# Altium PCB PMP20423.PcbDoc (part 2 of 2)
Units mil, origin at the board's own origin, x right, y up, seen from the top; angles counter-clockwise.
Board outline 2175 x 2115 mil, 4 copper layers (Top Layer, Signal Layer 1, Signal Layer 2, Bottom Layer), stack 82.634 mil thick; 73 components, 45 nets, 246 pads, 105 vias.
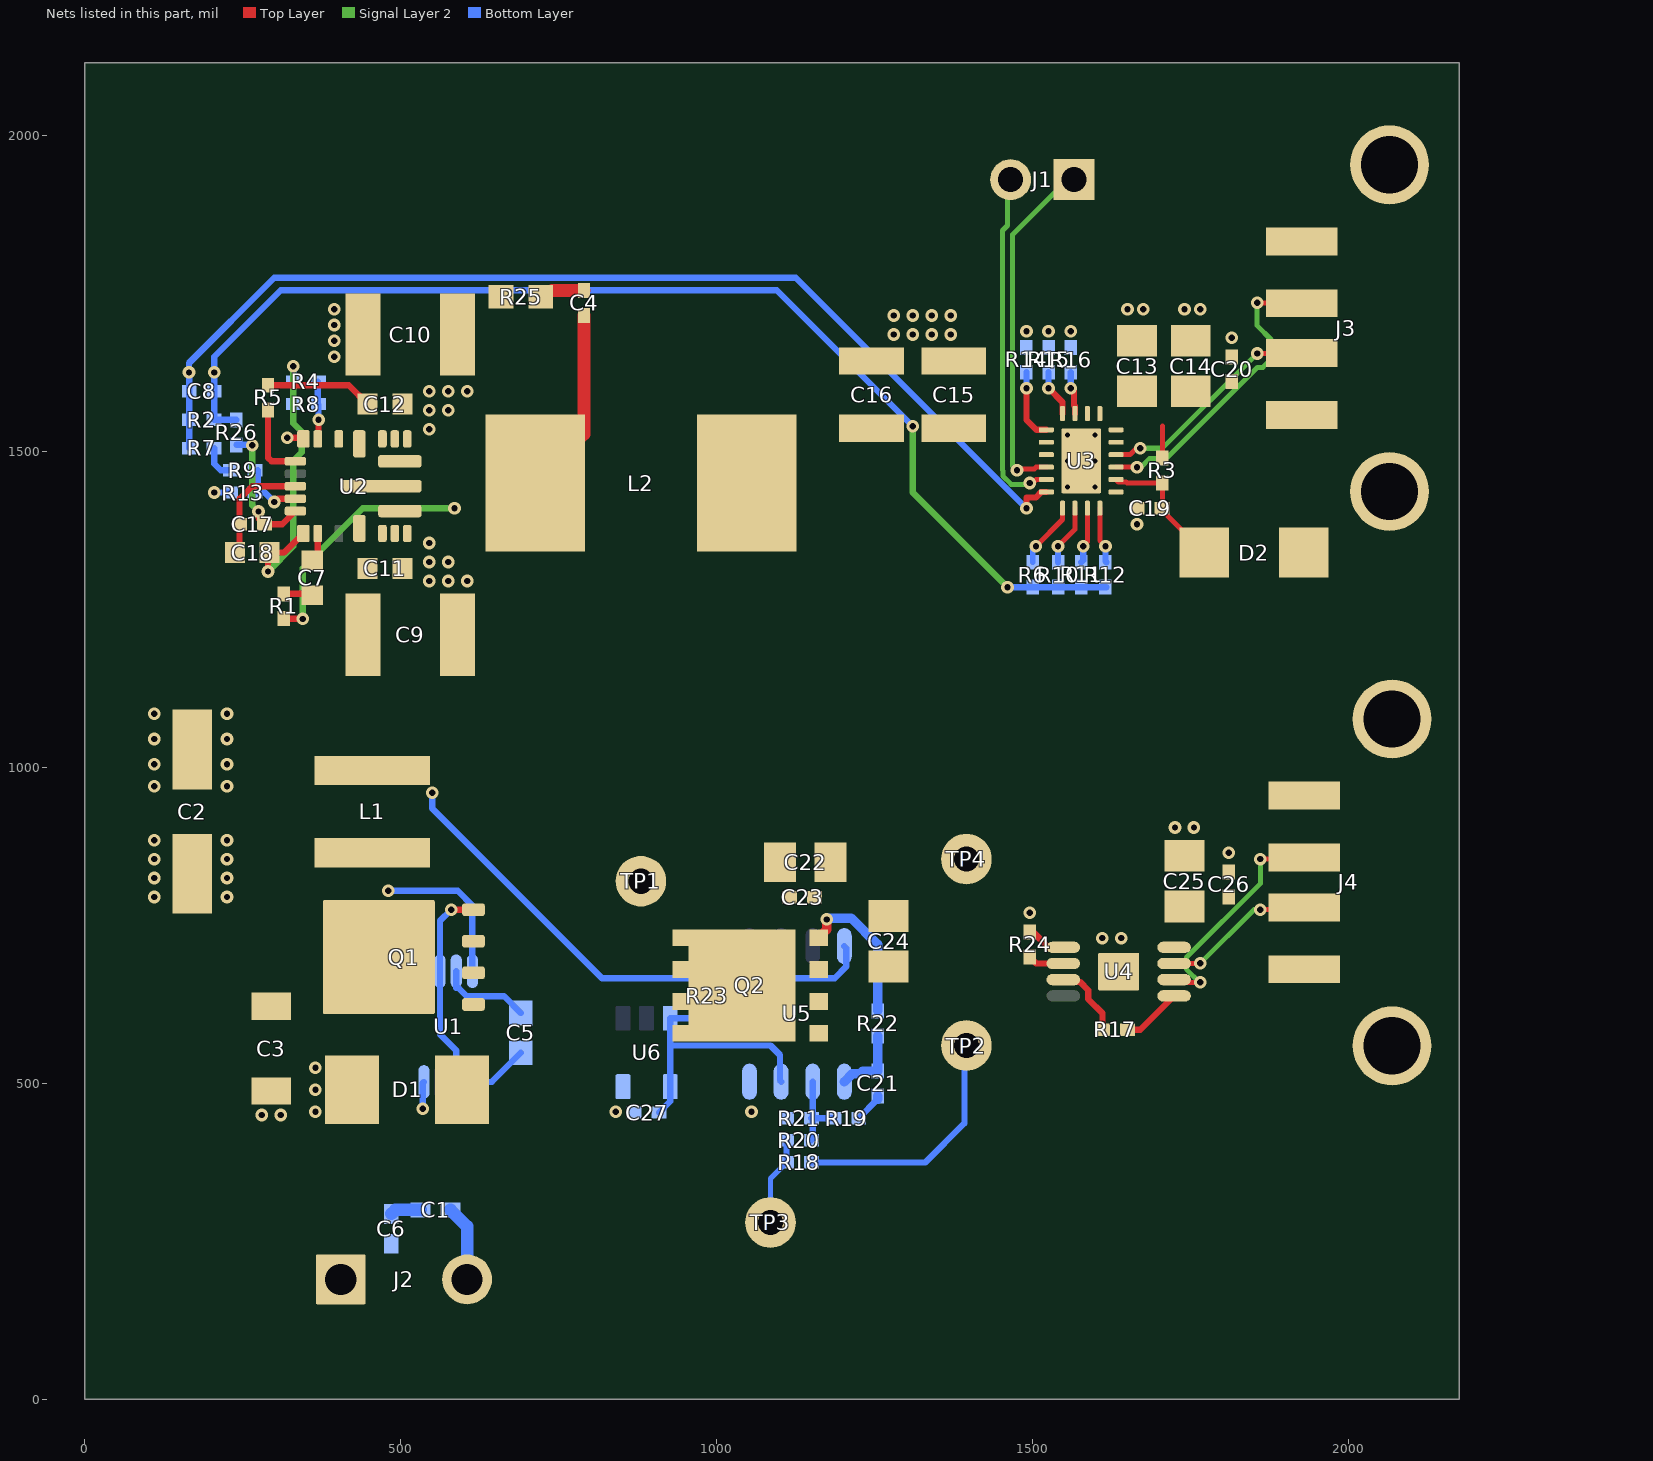
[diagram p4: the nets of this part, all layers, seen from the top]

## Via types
v1: diameter 20, hole 10, Top Layer to Bottom Layer, tented both sides, 99 vias
v2: diameter 19.68, hole 7.87, Top Layer to Bottom Layer, 6 vias

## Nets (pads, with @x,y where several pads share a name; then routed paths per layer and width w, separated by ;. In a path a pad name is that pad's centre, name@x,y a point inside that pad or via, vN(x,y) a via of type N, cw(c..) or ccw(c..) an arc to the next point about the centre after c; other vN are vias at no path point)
5VX: C8.1 C15.1 C16.1 C22.1 C23.1 L2.2 Q2.5 Q2.6 Q2.7 Q2.8 Q2.10 R2.2 R6.2 R10.2 R11.2 R12.2 R26.1 TP1.1 U3.2 U3.3 | length 1846.6
  Signal Layer 2 w10: v1(1310,1540) 1310,1435 v1(1460,1285)
  Bottom Layer w10: R26.1@240,1549.68 239.68,1550 R2.2@204.69,1550 205,1550.31 v1(205,1625) 205,1650 310,1755 1095,1755 v1(1310,1540) ; v1@1460.31,1285.31 1486.65,1285.31 1531.65,1285.31 R11.2@1576.65,1285.31 R12.2@1616.65,1285.31
CS: C8.2 R2.1 R7.2 U3.6 | length 1719
  Top Layer w10: v1(1490,1410) 1490,1427 1504.53,1427 1513.31,1435.79 U3.6@1521.54,1435.79
  Bottom Layer w10: v1(165,1625) 165,1640 300,1775 1125,1775 v1(1490,1410) ; R7.2@165.31,1505 C8.2@165.31,1595 v1@165.31,1624.69
DM1: J3.2 U3.14 | length 354.1
  Top Layer w8: U3.14@1631.77,1494.84 1653.73,1494.84 v1@1663.89,1505 ; v1(1855,1655) 1924.78,1655 J3.2@1925.41,1655.63
  Signal Layer 2 w8: v1(1670,1505) 1705,1505 v1(1855,1655)
DM1_H: J1.1 U3.4 | length 557.6
  Top Layer w8: v1(1475,1470) 1477.47,1472.47 1502.47,1472.47 1505.16,1475.16 U3.4@1521.54,1475.16
  Signal Layer 2 w8: v1(1475,1470) 1468,1477 1468,1843 1555,1930 J1.1@1565,1930
DP1: J3.3 U3.13 | length 484.8
  Top Layer w8: U3.13@1631.77,1475.16 v1@1664.84,1475.16 ; v1(1855,1735) 1924.78,1735 J3.3@1925.41,1734.37
  Signal Layer 2 w8: v1(1665,1475) 1671.11,1475 1685.11,1489 1711.63,1489 1855.63,1633 1864.11,1633 1877,1645.89 1877,1677 1855,1699 v1(1855,1735)
DP1_H: J1.2 U3.5 | length 554
  Top Layer w8: v1(1495,1450) 1500,1450 1505.47,1455.47 U3.5@1521.54,1455.47
  Signal Layer 2 w8: J1.2@1470,1930 1460,1920 1460,1857.63 1452,1849.63 1452,1470.37 1453,1469.37 1453,1460.89 1465.89,1448 1493,1448 v1(1495,1450)
GND: C2.2 C3.2 C6.2 C9.2 C10.2 C11.2 C12.2 C13.2 C14.2 C15.2 C16.2 C17.1 C18.2 C19.2 C20.2 C22.2 C23.2 C24.2 C25.2 C26.2 C27.2 D1.1 D2.1 J2.1 J3.4 J3.5 J3.6 J4.4 J4.5 J4.6 R8.1 R13.1 R14.1 R15.1 R16.1 R21.1 R24.1 R25.1 TP4.1 U2.5 U2.6 U2.7 U2.8 U2.10 U2.11 U2.12 U2.13 U2.17 U2.20 U3.11 U3.17 U3.18 U3.21@1576.65,1485 U4.1 U4.9 U5.4 U6.5 | length 295.8
  Top Layer w10: C18.2@235,1345 245,1355 245,1425 265,1445 312.48,1445 U2.20@333.19,1445 ; v1(320.39,1521.77) 344.02,1521.77 U2.17@345.98,1519.8 ; R24.1@1495,739.68 1500.32,739.68 1524.61,715.39 U4.1@1548.4,715.39
  Bottom Layer w10: v1(205,1435) R13.1@230.32,1435
  other v1: 280,450 310,450 365,455 840,455 1055,455 365,490 365,525 1610,730 1640,730 1495,770 110,795 225,795 110,825 225,825 110,855 225,855 1810,865 110,885 225,885 1725,905 1755,905 545,1295 575,1295 605,1295 545,1325 575,1325 545,1355 1665,1385 545,1535 545,1565 575,1565 545,1595 575,1595 605,1595 1815,1680 1280,1685 1310,1685 1340,1685 1370,1685 1490,1690 1525,1690 1560,1690 1280,1715 1310,1715 1340,1715 1370,1715 1650,1725 1675,1725 1740,1725 1765,1725
  other v2: 1555,1443.66 1598.31,1443.66 1555,1485 1598.31,1485 1555,1526.34 1598.31,1526.34
NetC1_2: C1.2 C6.1 | length 49
  Bottom Layer w20: C6.1@485,293.62 491.38,300 C1.2@531.38,300
NetC3_1: C3.1 L1.1 Q1.5 Q1.6 Q1.7 Q1.8 Q1.9@465.43,700 U1.8 | length 247.1
  Bottom Layer w10: v1(480,805) 590,805 613.39,781.61 U1.8@613.39,677.6
NetC4_1: C4.1 L2.1 R1.1 U2.9 | length 686.4
  Top Layer w10: R1.1@315,1235.32 v1@344.68,1235.32
  Top Layer w20: L2.1@712.68,1450 790,1527.32 C4.1@790,1715.32
  Signal Layer 2 w10: v1(345,1235) 345,1315 390,1360 440,1410 v1(585,1410)
NetC4_2: C4.2 R25.2 | length 64
  Top Layer w10: R25.2@730,1745 R25.2@739.69,1754.69
  Top Layer w20: R25.2@739.69,1754.69 C4.2@790,1754.69
NetC5_1: C5.1 U1.7 | length 145.3
  Bottom Layer w10: U1.7@587.8,677.6 587.8,651.02 591.53,651.02 591.53,650.83 604.33,638.02 663.47,638.02 C5.1@690,611.5
NetC5_2: C5.2 U1.1 | length 95.7
  Bottom Layer w10: U1.1@613.39,502.4 643.9,502.4 C5.2@690,548.5
NetC7_1: C7.1 R1.2 | length 45.9
  Top Layer w10: R1.2@315,1274.69 357.76,1274.69 C7.1@360,1272.44
NetC7_2: C7.2 U2.2 | length 46.2
  Top Layer w10: C7.2@360,1327.56 368.62,1336.18 U2.2@368.62,1370.2
NetC17_2: C17.2 R26.2 U2.22 | length 211
  Top Layer w10: v1(275,1405) 275,1394.69 C17.2@284.69,1385 ; C17.2@288.62,1385 312.56,1385 U2.22@333.19,1405.63
  Signal Layer 2 w10: v1(265,1510) 265,1415 v1(275,1405)
  Bottom Layer w10: R26.2@240,1510.31 v1@264.69,1510.31
NetC19_1: C19.1 D2.2 R3.1 U3.12 | length 213.4
  Top Layer w8: U3.12@1631.77,1455.47 1635.52,1451.72 1647.4,1451.72 1648.81,1450.32 R3.1@1705,1450.32 1705,1410.32 C19.1@1704.68,1410 1704.68,1406.57 D2.2@1771.26,1340
NetC21_1: C21.1 R22.1 U5.1 | length 115.8
  Bottom Layer w15: U5.1@1201.86,502.72 1214.15,515 1226.45,515 1231.14,519.68 C21.1@1255,519.68 R22.1@1255,575.32
NetC21_2: C21.2 R19.2 | length 47.9
  Bottom Layer w10: R19.2@1224.69,445 C21.2@1255,475.31
  Bottom Layer w15: C21.2@1255,475.31 C21.2@1255,480.31
NetC24_1: C24.1 Q2.1 Q2.2 Q2.3 R17.2 R18.2 TP2.1 U4.3 | length 504.3
  Top Layer w10: U4.3@1548.4,664.2 1557.26,664.2 1560.99,660.47 1575.17,660.47 1587.98,647.67 1587.98,633.49 1610.31,611.15 R17.2@1610.31,585
  Bottom Layer w10: R18.2@1149.69,375 1330,375 1391.86,436.86 TP2.1@1391.86,555
NetC27_1: C27.1 R23.1 U5.3 U6.3 U6.4 | length 505.4
  Bottom Layer w10: C27.1@908.75,454 926.46,471.72 U6.4@926.46,494.87 ; R23.1@984.06,611.44 975.76,603.13 U6.3@926.46,603.13 U6.4@926.46,494.87 ; U5.3@1101.86,502.72 1100,504.58 1100,545 1085,560 926.46,560 U6.4@926.46,494.87
NetJ4_2: J4.2 U4.7 | length 242.3
  Top Layer w8: U4.7@1723.6,689.8 v1@1764.8,689.8 ; v1(1860,775) 1925.78,775 J4.2@1929.41,778.63
  Signal Layer 2 w8: v1(1765,690) 1850,775 v1(1860,775)
NetJ4_3: J4.3 U4.6 | length 365.7
  Top Layer w8: U4.6@1723.6,664.2 1727.8,660 v1(1765,660) ; v1(1860,855) 1927.04,855 J4.3@1929.41,857.37
  Signal Layer 2 w8: v1@1763.89,660 1743,680.89 1743,699.11 1860,816.11 v1(1860,855)
NetQ1_4: Q1.4 U1.2 U1.6 | length 325.6
  Top Layer w10: v1(580,775) Q1.4@615.04,775
  Bottom Layer w10: v1(580,775) 562.2,757.2 U1.6@562.2,677.6 562.2,577.8 587.8,552.2 U1.2@587.8,502.4
NetQ2_4: Q2.4 R22.2 | length 238.2
  Top Layer w15: Q2.4@1161.17,730.49 1174.11,743.43 v1(1174.11,759.53)
  Bottom Layer w15: v1(1174.11,759.53) 1175.91,761.33 1213.17,761.33 1254.5,720 1254.5,615.18 R22.2@1255,614.69
NetR4_1: R4.1 R8.2 U2.16 | length 91.3
  Top Layer w10: U2.16@368.83,1519.8 370,1520.98 v1(370,1550)
  Bottom Layer w10: R4.1@368.62,1610 368.62,1575 370,1573.62 v1(370,1550)
NetR5_2: R5.2 U2.18 | length 120.8
  Top Layer w10: R5.2@290,1565.31 290,1490 295.63,1484.37 U2.18@333.19,1484.37
NetR6_1: R6.1 U3.7 | length 98
  Top Layer w8: v1(1505,1350) 1547.13,1392.13 U3.7@1547.13,1410.2
  Bottom Layer w8: R6.1@1500,1324.68 v1@1500,1345
NetR7_1: R7.1 R9.2 | length 54.6
  Bottom Layer w10: R7.1@204.68,1505 204.68,1480.32 215,1470 R9.2@230.31,1470
NetR9_1: R9.1 R13.2 U2.21 | length 95.5
  Top Layer w10: v1@305.31,1425.31 U2.21@333.19,1425.31
  Bottom Layer w10: R9.1@273.62,1470 273.62,1435 285,1435 v1(300,1420)
NetR10_1: R10.1 U3.8 | length 96.6
  Top Layer w8: v1(1540,1350) 1566.81,1376.81 U3.8@1566.81,1410.2
  Bottom Layer w10: R10.1@1540,1324.68 v1(1540,1350)
NetR11_1: R11.1 U3.9 | length 80.4
  Top Layer w8: v1@1586.5,1356.5 U3.9@1586.5,1410.2
  Bottom Layer w10: R11.1@1576.65,1324.68 1580,1328.03 v1(1580,1350)
NetR12_1: R12.1 U3.10 | length 89.8
  Top Layer w8: U3.10@1606.18,1410.2 1606.18,1358.82 v1(1615,1350)
  Bottom Layer w10: v1(1615,1350) 1615,1326.34 R12.1@1616.65,1324.68
NetR14_2: R14.2 U3.1 | length 113.4
  Top Layer w10: v1(1490,1600) 1490,1550 1505.79,1534.21 U3.1@1521.54,1534.21
  Bottom Layer w10: v1(1490,1600) R14.2@1490,1625.31
NetR15_2: R15.2 U3.20 | length 74.7
  Top Layer w10: v1(1525,1600) 1547.13,1577.87 U3.20@1547.13,1559.8
  Bottom Layer w10: v1(1525,1600) R15.2@1525,1625.31
NetR16_2: R16.2 U3.19 | length 68.3
  Top Layer w10: v1(1560,1600) 1565.13,1594.87 1565.13,1573.3 1566.81,1571.61 U3.19@1566.81,1559.8
  Bottom Layer w10: v1(1560,1600) R16.2@1560,1625.31
NetR17_1: R17.1 U4.5 | length 96.1
  Top Layer w10: R17.1@1649.68,585 1669.98,585 U4.5@1723.6,638.61
NetR18_1: R18.1 R20.2 TP3.1 | length 140.5
  Bottom Layer w8: TP3.1@1085,280 1085,349.68 R18.1@1110.32,375
  Bottom Layer w10: R18.1@1110.32,375 R20.2@1110.31,410
NetR19_1: R19.1 R20.1 R21.2 U5.2 | length 129.2
  Bottom Layer w10: R20.1@1149.68,410 1151.86,412.18 R21.2@1151.86,445 ; R21.2@1149.69,445 R21.2@1151.86,445 ; U5.2@1151.86,502.72 R21.2@1151.86,445 ; R19.1@1185.32,445 R21.2@1151.86,445
NetR24_2: R24.2 U4.2 | length 57.8
  Top Layer w10: R24.2@1495,700.31 1505.52,689.8 U4.2@1548.4,689.8
VBATT: C1.1 D1.2 J2.2 Q1.1 Q1.2 Q1.3 U1.4 | length 139
  Bottom Layer w10: v1(535,460) 535,500.79 U1.4@536.61,502.4
  Bottom Layer w20: C1.1@578.62,300 605,273.62 J2.2@605,215
VBUS_LOCAL: C25.1 C26.1 J4.1 U4.8
VBUS_REMOTE: C13.1 C14.1 C20.1 J3.1 R3.2 U3.15 U3.16 | length 50.3
  Top Layer w8: R3.2@1705,1489.69 1705,1540
VCC: C18.1 R4.2 U2.1 | length 472.7
  Top Layer w10: v1(290,1310) 290,1333.5 296.5,1340 315.79,1340 U2.1@345.98,1370.2 U2.1@345.98,1369.49
  Signal Layer 2 w10: v1(290,1310) 330,1350 330,1485.46 343.39,1498.85 343.39,1531.3 330,1544.69 v1(330,1635)
  Bottom Layer w10: R4.2@330.31,1610 v1@330.31,1634.69
VIN: C2.1 C9.1 C10.1 C11.1 C12.1 L1.2 R5.1 R23.2 U2.4 U2.14 U2.15 U5.8 | length 1002.2
  Top Layer w10: R5.1@290,1604.68 417.76,1604.68 C12.1@447.44,1575
  Bottom Layer w10: v1(550,960) 550,935 818.44,666.56 R23.2@984.06,666.56 1186.56,666.56 1205,685 1205,714.15 U5.8@1201.86,717.28
  other v1: 110,970 225,970 110,1005 225,1005 110,1045 225,1045 110,1085 225,1085 395,1650 395,1675 395,1700 395,1725
pads on no net: Q1.9@449.88,642.91 Q1.9@449.88,700 Q1.9@449.88,757.09 Q1.9@483.35,700 Q1.9@519.96,642.91 Q1.9@519.96,700 Q1.9@519.96,757.09 U1.3 U1.5 U2.3 U2.4A U2.4B U2.8A U2.8B U2.9A U2.9B U2.9C U2.9D U2.10A U2.10B U2.14A U2.14B U2.19 U3.21@1576.65,1458.43 U3.21@1576.65,1511.57 U4.4 U5.5 U5.6 U5.7 U6.1 U6.2

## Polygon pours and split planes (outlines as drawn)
GND on Top Layer "GND_L01_P022" (solid, remove dead copper, pour order 22): 0,2115 0,0 2175,0 2175,2115
VBUS_LOCAL on Top Layer "VBUS_LOCAL_L01_P020" (solid, remove dead copper, pour order 20): 1685,815 1685,705 1735,705 1815,625 2025,625 2025,745 1865,745 1830,780 1830,815
VBUS_REMOTE on Top Layer "VBUS_REMOTE_L01_P018" (solid, remove dead copper, pour order 18): 1615,1630 1615,1465 2005,1465 2005,1620 1995,1630
NetC24_1 on Top Layer "NETC24_1_L01_P016" (solid, remove dead copper, pour order 16): 1145,720 1435,720 1480,675 1575,675 1575,655 1520,655 1485,620 1485,390 1145,390
5VX on Top Layer "5VX_L01_P014" (solid, remove dead copper, pour order 14): 815,520 1135,520 1135,865 1440,1170 1440,1470 1460,1490 1530,1490 1530,1525 1490,1525 1435,1580 900,1580 900,1180 815,1095
VIN on Top Layer "VIN_L01_P010" (solid, remove dead copper, pour order 10): 380,1490 450,1490 450,1540 475,1565 475,1775 380,1775
NetC4_1 on Top Layer "NETC4_1_L01_P008" (solid, remove dead copper, pour order 8): 405,1455 405,1435 535,1435 635,1335 800,1335 800,1565 635,1565 525,1455
NetC3_1 on Top Layer "NETC3_1_L01_P004" (solid, remove dead copper, pour order 4): 250,900 250,580 595,580 595,900
VIN on Top Layer "VIN_L01_P002" (solid, remove dead copper, pour order 2): 0,1150 0,950 560,950 560,1075 525,1110 525,1345 465,1345 455,1355 455,1400 415,1400 415.02,1305.02 390,1280 390,1180 355,1145 350,1150
VBATT on Top Layer "VBATT_L01_P000" (solid, remove dead copper, pour order 0): 590,740 590,608.5 510,528.5 510,0 800,0 800,740
GND on Signal Layer 2 "GND_L03_P028" (solid, remove dead copper, pour order 28): 0,2115 5,2110 5,0 2185,0 2185,2110 10,2110 5,2115
VIN on Signal Layer 2 "VIN_L03_P012" (solid, remove dead copper, pour order 12): 245,950 245,1595 285,1635 415,1635 415,1760 25,1760 25,950
GND on Signal Layer 1 "GND_L02_P024" (solid, remove dead copper, pour order 24): 2180,2115 2180,-5 5,-5 0,0 0,2115
GND on Bottom Layer "GND_L04_P026" (solid, remove dead copper, pour order 26): 5,2115 0,2110 0,5 2165,5 2175,-5 2175,2120 0,2120

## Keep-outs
Keep-Out Layer:
  lines w10: -5,0 ccw(c0,0) 0,-5 ; -5,0 ccw(c0,0) 0,-5 ; -5,0 -5,2115 ; -5,2115 cw(c0,2115) 0,2120 ; -5,2115 cw(c0,2115) 0,2120 ; 0,-5 2175,-5 ; 0,2120 2175,2120 ; 2175,-5 ccw(c2175,0) 2180,0 ; 2175,-5 ccw(c2175,0) 2180,0 ; 2175,2120 cw(c2175,2115) 2180,2115 ; 2175,2120 cw(c2175,2115) 2180,2115 ; 2180,0 2180,2115
  text ".Layer_Name" at 577,-858.49 h60

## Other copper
Top Layer:
  pour cut-out: 900,1580 900,1330 800,1330 800,1580
  text ".Layer_Name" at 577,-858.49 h60
Bottom Layer:
  text ".Layer_Name" at 577,-858.49 h60

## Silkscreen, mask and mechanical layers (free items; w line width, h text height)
Top Overlay:
  text ".Layer_Name" at 577,-858.49 h60
Bottom Overlay:
  text ".Layer_Name" at 577,-858.49 h60
Top Paste:
  text ".Layer_Name" at 577,-858.49 h60
Bottom Paste:
  text ".Layer_Name" at 577,-858.49 h60
Top Solder:
  text ".Layer_Name" at 577,-858.49 h60
  text ".Layer_Name" at 577,-858.49 h60
Bottom Solder:
  text ".Layer_Name" at 577,-858.49 h60
Drill Guide:
  text ".Layer_Name" at 577,-858.49 h60
M1 Board Outline:
  the board outline again, w10
  text ".Layer_Name" at 577,-858.49 h60
M2 Board Dimensions:
  rectangle: 0,-275 125,-150
  rectangle: 125,-400 500,-275
  lines w7: 0,-275 1000,-275 ; 125,-400 125,-150 ; 250,-400 250,-150 ; 500,-400 500,-150 ; 750,-400 750,-150 ; 0,-400 1000,-400 1000,-150 0,-150 0,-400
  text ".Layer_Name" at 577,-858.49 h60
M3 3D STEP Top:
  text ".Layer_Name" at 577,-858.49 h60
M4 3D STEP Bottom:
  text ".Layer_Name" at 577,-858.49 h60
M5 Assembly Top:
  lines w10: -292,-930.17 6308,-930.17 ; -292,-726.83 6310,-726.83 ; -292,-523.5 -292,-1133.5 3713,-1133.5 6310,-1133.5 6310,-523.5 -291.5,-523.5 -291.5,-1133.5 1284,-1133.5 ; 2173,-1133.5 2173,-523.5 ; 3440,-726.83 3440,-523.5 ; 4280,-726.83 4280,-523.5 ; 4902,-1140 4902,-937.17
  text "COMPONENTS MARKED 'DNP' SHOULD NOT BE POPULATED." at 1153.5,-318.5 h60
  text "ASSEMBLY VARIANT:" at 1153,-434 h60
  text ".VariantName" at 2189,-434 h60
  text "PCB VIEWED FROM TOP SIDE" at -228.5,-655.67 h60
  text "BOARD #:" at 2248,-655.67 h60
  text ".PRJ_Number" at 2793.5,-655.67 h60
  text "REV:" at 3638,-655.67 h60
  text ".PCB_Rev" at 3929.5,-655.67 h60
  text "SVN REV:" at 4476,-655.67 h60
  text ".VersionControl_RevNumber" at 4982,-655.67 h60
  text "TID #:" at 2248,-859 h60
  text ".TID" at 2793.5,-859 h60
  text "PLOT NAME =" at -228.5,-1064.34 h60
  text ".plot_File_Name" at 577,-1064.34 h60
  text "GENERATED    :" at 2250,-1064.34 h60
  text ".Print_Date" at 3119.5,-1064.34 h60
  text ".Print_Time" at 3848.5,-1064.34 h60
  text "TEXAS INSTRUMENTS" at 5113,-1064.34 h60
M6 Assembly Bottom:
  lines w10: -292.5,-727.33 6309.5,-727.33 ; -290.5,-930.67 6309.5,-930.67 ; 1115.5,-1140.5 1115.5,-937.67 ; 1737.5,-727.33 1737.5,-524 ; 2577.5,-727.33 2577.5,-524 ; 3844.5,-1134 3844.5,-524 ; 4733.5,-1134 6309,-1134 6309,-524 -292.5,-524 -292.5,-1134 2304.5,-1134 6309.5,-1134 6309.5,-524
  text "COMPONENTS MARKED 'DNP' SHOULD NOT BE POPULATED." at 6102,-318 h60
  text ".VariantName" at 5058,-434 h60
  text "ASSEMBLY VARIANT:" at 6097,-434 h60
  text ".VersionControl_RevNumber" at 1035.5,-656.17 h60
  text "SVN REV:" at 1541.5,-656.17 h60
  text ".PCB_Rev" at 2088,-656.17 h60
  text "REV:" at 2379.5,-656.17 h60
  text ".PRJ_Number" at 3224,-656.17 h60
  text "BOARD #:" at 3769.5,-656.17 h60
  text "PCB VIEWED FROM BOTTOM SIDE" at 6246,-656.17 h60
  text ".TID" at 3224,-859.5 h60
  text "TID #:" at 3769.5,-859.5 h60
  text "TEXAS INSTRUMENTS" at 904.5,-1064.84 h60
  text ".Print_Time" at 2169,-1064.84 h60
  text ".Print_Date" at 2898,-1064.84 h60
  text "GENERATED    :" at 3767.5,-1064.84 h60
  text ".plot_File_Name" at 5440.5,-1064.84 h60
  text "PLOT NAME =" at 6246,-1064.84 h60
M9 Title Sheet:
  drawing of 57 lines, arcs and shapes, not listed
  text "1" at 739.84,8036.5 h70
  text "2" at 3235.5,8036.5 h70
  text "3" at 5724.84,8036.5 h70
  text "4" at 8231.51,8036.5 h70
  text "5" at 10730.5,8036.5 h70
  text "6" at 13235.5,8036.5 h70
  text "A" at -416.5,6893.5 h70
  text "A" at 14383.5,6893.5 h70
  text "B" at -416.5,4513.5 h70
  text "B" at 14383.5,4513.5 h70
  text "C" at -416.5,2138.5 h70
  text "C" at 14383.5,2138.5 h70
  text "PROJECT TITLE:" at 11343.5,277.5 h45
  text ".PRJ_Title" at 11393.5,144.17 h70
  text "DESIGNED FOR:" at 11343.5,-23.5 h45
  text ".PRJ_Customer" at 11393.5,-163.5 h70
  text "D" at -416.5,-231.5 h70
  text "D" at 14383.5,-231.5 h70
  text "FILE NAME:" at 11343.5,-323.5 h45
  text ".PCB_File_Name_No_Path" at 11393.5,-443.5 h70
  text "Texas Instruments (TI) and/or its licensors do not warrant the accuracy or completeness of this specification" at 6374,-605.34 h45
  text "ENGINEER:" at 11343.5,-613.5 h45
  text "LAYOUT BY:" at 12848.5,-613.5 h45
  text "or any information contained therein. TI and/or its licensors do not warrant that this design will meet" at 6329.01,-718 h45
  text ".PRJ_Engineer" at 11393.5,-768.49 h70
  text ".PCB_Layout" at 12899,-768.49 h70
  text "the specifications, will be suitable for your application or fit for any particular purpose, or will operate in" at 6329.01,-830.67 h45
  text ".Layer_Name" at 577,-858.49 h60
  text "ALTIUM DESIGNER VERSION:" at 12848.5,-923.5 h45
  text "an implementation. TI and/or its licensors do not warrant that the design is production worthy. You should" at 6329.01,-943.33 h45
  text "completely validate and test your design implementation to confirm the system functionality for your application." at 6374,-1056 h45
  text ".print_Scale" at 11393.5,-1056.83 h70
  text ".Application_BuildNumber" at 12899,-1056.83 h70
  text "1" at 739.84,-1263.5 h70
  text "2" at 3235.5,-1263.5 h70
  text "3" at 5724.84,-1263.5 h70
  text "4" at 8231.51,-1263.5 h70
  text "5" at 10730.5,-1263.5 h70
  text "6" at 13235.5,-1263.5 h70
M10 Fab Notes:
  drawing of 173 lines, arcs and shapes, not listed
  text "DESIGN INFORMATION" at 12377.02,6201 h60
  text "MIN. TRACK WIDTH:" at 11732.46,6021 h60
  text "8" at 12828.7,6021 h60
  text "MIL" at 12983.46,6021 h60
  text "MIN. CLEARANCE:" at 11732.46,5889 h60
  text "0.2" at 12768.7,5889 h60
  text "mm" at 12983.46,5889 h60
  text "MIN. VIA PAD SIZE:" at 11732.46,5757 h60
  text "24" at 12798.71,5757 h60
  text "MIL" at 12983.46,5757 h60
  text "0.05mm (2MIL)" at 12427.46,5615.29 h60
  text "MINIMUM ANNULAR RING" at 11403.23,5611 h60
  text "EXTERNAL" at 13135.46,5611 h60
  text "PER" at 11603.23,5493 h60
  text "IPC-D-275 CLASS 2 LEVEL C" at 11823.23,5493 h60
  text "MIL, HOLES" at 13311.46,5380.71 h60
  text "+/-" at 12919,5380 h60
  text "+/-" at 13773,5380 h60
  text "REGISTRATION TOLERANCES:" at 11403.23,5375 h60
  text "METAL" at 12603,5375 h60
  text "5" at 13179.2,5375 h60
  text "3" at 14012.2,5375 h60
  text "MIL" at 14128.46,5375 h60
  text "+/-" at 13773,5262 h60
  text "HOLE SIZE TOLERANCE (UNLESS OTHERWISE SPECIFIED):" at 11403.23,5257 h60
  text "3" at 14012.2,5257 h60
  text "MIL" at 14128.46,5257 h60
  text "MATERIAL:" at 11328.46,5047.54 h60
  text "FR-4 High Tg" at 12314.9,4907.21 h60
  text "FR-408" at 11749.46,4898.64 h60
  text "OTHER" at 13237.46,4898.64 h60
  text "X" at 12160,4895 h60
  text "62 MIL (1.6mm) +/-10%" at 12069.56,4735.92 h60
  text "THICKNESS:" at 11403.23,4731.64 h60
  text "X" at 11941.4,4731.64 h60
  text "OTHER" at 13354.46,4731.64 h60
  text "TOLERANCE:" at 11403.23,4573.64 h60
  text "X" at 12242.53,4573.64 h60
  text "ANSI IPC-6012 TYPE 3 CLASS 2" at 12429.48,4573.64 h60
  text "OTHER +/-" at 12429.46,4417.64 h60
  text "BOW & TWIST:" at 11403.23,4260.64 h60
  text "X" at 12242.53,4260.64 h60
  text "ANSI IPC-6012 TYPE 3 CLASS 2" at 12429.48,4260.64 h60
  text "OTHER +/-" at 12429.46,4102.13 h60
  text "DRILLING:" at 11328.46,3963.64 h60
  text "REFERENCE:" at 11403.23,3846.64 h60
  text "X" at 12051.46,3846.64 h60
  text "AS SHOWN" at 12238.46,3846.64 h60
  text "X" at 12952.46,3846.64 h60
  text "NC_DRILL FILES" at 13089.46,3846.64 h60
  text "PTH COPPER THICKNESS:" at 11403.23,3688.64 h60
  text "X" at 12533.46,3688.64 h60
  text "20-30 um" at 12670.46,3688.64 h60
  text "OTHER" at 13387.46,3688.64 h60
  text "BOARD FINISH:" at 11328.46,3529.64 h60
  text "SILKSCREEN:" at 11483.68,3411.64 h60
  text "X" at 12432.46,3411.64 h60
  text "TOP" at 12558.46,3411.64 h60
  text "X" at 12942.46,3411.64 h60
  text "BOTTOM" at 13069.46,3411.64 h60
  text "SILKSCREEN COLOR:" at 11483.68,3244.64 h60
  text "X" at 12431.42,3244.64 h60
  text "WHITE" at 12558.46,3244.64 h60
  text "OTHER" at 13069.46,3244.64 h60
  text "GREEN" at 12689.46,3085.44 h60
  text "OTHER" at 13307.46,3085.44 h60
  text "BLUE" at 13632,3082 h60
  text "X" at 13150,3080 h60
  text "SOLDER RESIST COLOR:" at 11483.68,3074.64 h60
  text "X" at 12562.42,2915.44 h60
  text "MATTE" at 12689.46,2915.44 h60
  text "SEMI-GLOSS" at 13307,2914.8 h60
  text "IMMERSION GOLD (ENIG)" at 12389.46,2726.92 h60
  text "ENEPIG" at 13727,2723.64 h60
  text "SURFACE FINISH:" at 11328.46,2722.64 h60
  text "X" at 12202.51,2722.64 h60
  text "IMM. TIN/SILVER OR EQUIV" at 11658,2565.64 h60
  text "OTHER" at 13089.46,2565.64 h60
  text "ARRAY/PANEL:" at 11328.46,2386.64 h60
  text "CUT AND TRIM PER M1 BOARD OUTLINE" at 12389.46,2382.35 h60
  text "N.C. ROUTE" at 12389.46,2230.64 h60
  text "X" at 13068.46,2230.64 h60
  text "V. SCORE" at 13255.46,2230.64 h60
  text "CERTIFICATION:" at 11328.46,2093.64 h60
  text "MATERIALS AND WORKMANSHIP FOR ALL PCBS" at 12053.46,2093.64 h60
  text "TO MEET OR EXCEED THE REQUIREMENTS OF:" at 12053.46,1995.64 h60
  text "X" at 11679.96,1859.13 h60
  text "ANSI IPC-A-600F CLASS ->" at 11818.96,1859.13 h60
  text "X" at 13458.02,1859.13 h60
  text "2" at 13576.96,1859.14 h60
  text "1" at 13261.96,1857.64 h60
  text "3" at 13930.96,1857.64 h60
  text "X" at 12494.02,1699.64 h60
  text "RoHS" at 12630.96,1699.64 h60
  text "OTHER" at 13275.36,1699.64 h60
  text "PER ORDER" at 13672.42,1699.64 h60
  text "ALL BOARDS MUST MEET OR EXCEED UL94-V0 REQUIREMENTS." at 11356,1534 h60
  text "PCB MUST BEAR THE UL94V-0 UL REGISTERED MATERIAL ID NUMBER" at 11356,1414 h60
  text "ADDITIONAL REQUIREMENTS:" at 11328.46,1240.64 h60
  text "MICROSECTION:" at 11403.23,1125.64 h60
  text "YES" at 12308.96,1125.64 h60
  text "X" at 12600,970 h60
  text "REQUIRED" at 13170.46,969.49 h60
  text "BARE BOARD ELEC. TEST:" at 11403.23,966.64 h60
  text "NONE" at 12708.96,966.64 h60
  text "PER ORDER" at 13762.46,966.64 h60
  text ".Layer_Name" at 577,-858.49 h60
M11 Gerber Information:
  lines w10: -292,-930.17 6308,-930.17 ; -292,-726.83 6310,-726.83 ; -292,-523.5 -292,-1133.5 3713,-1133.5 6310,-1133.5 6310,-523.5 -291.5,-523.5 -291.5,-1133.5 1284,-1133.5 ; 2173,-1133.5 2173,-523.5 ; 3440,-726.83 3440,-523.5 ; 4280,-726.83 4280,-523.5 ; 4902,-1140 4902,-937.17
  text "ALL ARTWORK VIEWED FROM TOP SIDE" at -228.5,-655.67 h60
  text "BOARD #:" at 2248,-655.67 h60
  text ".PRJ_Number" at 2793.5,-655.67 h60
  text "REV:" at 3638,-655.67 h60
  text ".PCB_Rev" at 3929.5,-655.67 h60
  text "SVN REV:" at 4476,-655.67 h60
  text ".VersionControl_RevNumber" at 4982,-655.67 h60
  text "LAYER NAME =" at -228.5,-858.49 h60
  text "TID #:" at 2248,-859 h60
  text ".TID" at 2793.5,-859 h60
  text "PLOT NAME =" at -228.5,-1064.34 h60
  text ".plot_File_Name" at 577,-1064.34 h60
  text "GENERATED    :" at 2250,-1064.34 h60
  text ".Print_Date" at 3119.5,-1064.34 h60
  text ".Print_Time" at 3848.5,-1064.34 h60
  text "TEXAS INSTRUMENTS" at 5113,-1064.34 h60
M12 Stackup:
  text ".Layer_Name" at 577,-858.49 h60
M13 Component Bodies Top:
  text ".Layer_Name" at 577,-858.49 h60
M14 Component Bodies Bottom:
  text ".Layer_Name" at 577,-858.49 h60
M15 Courtyards Top:
  text ".Layer_Name" at 577,-858.49 h60
M16 Courtyards Bottom:
  text ".Layer_Name" at 577,-858.49 h60
Drill Drawing:
  text ".Layer_Name" at 577,-858.49 h60

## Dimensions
0,-400 to 1000,-400 on M2 Board Dimensions
0,0 to 0,2115 on M2 Board Dimensions
0,0 to 2175,0 on M2 Board Dimensions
